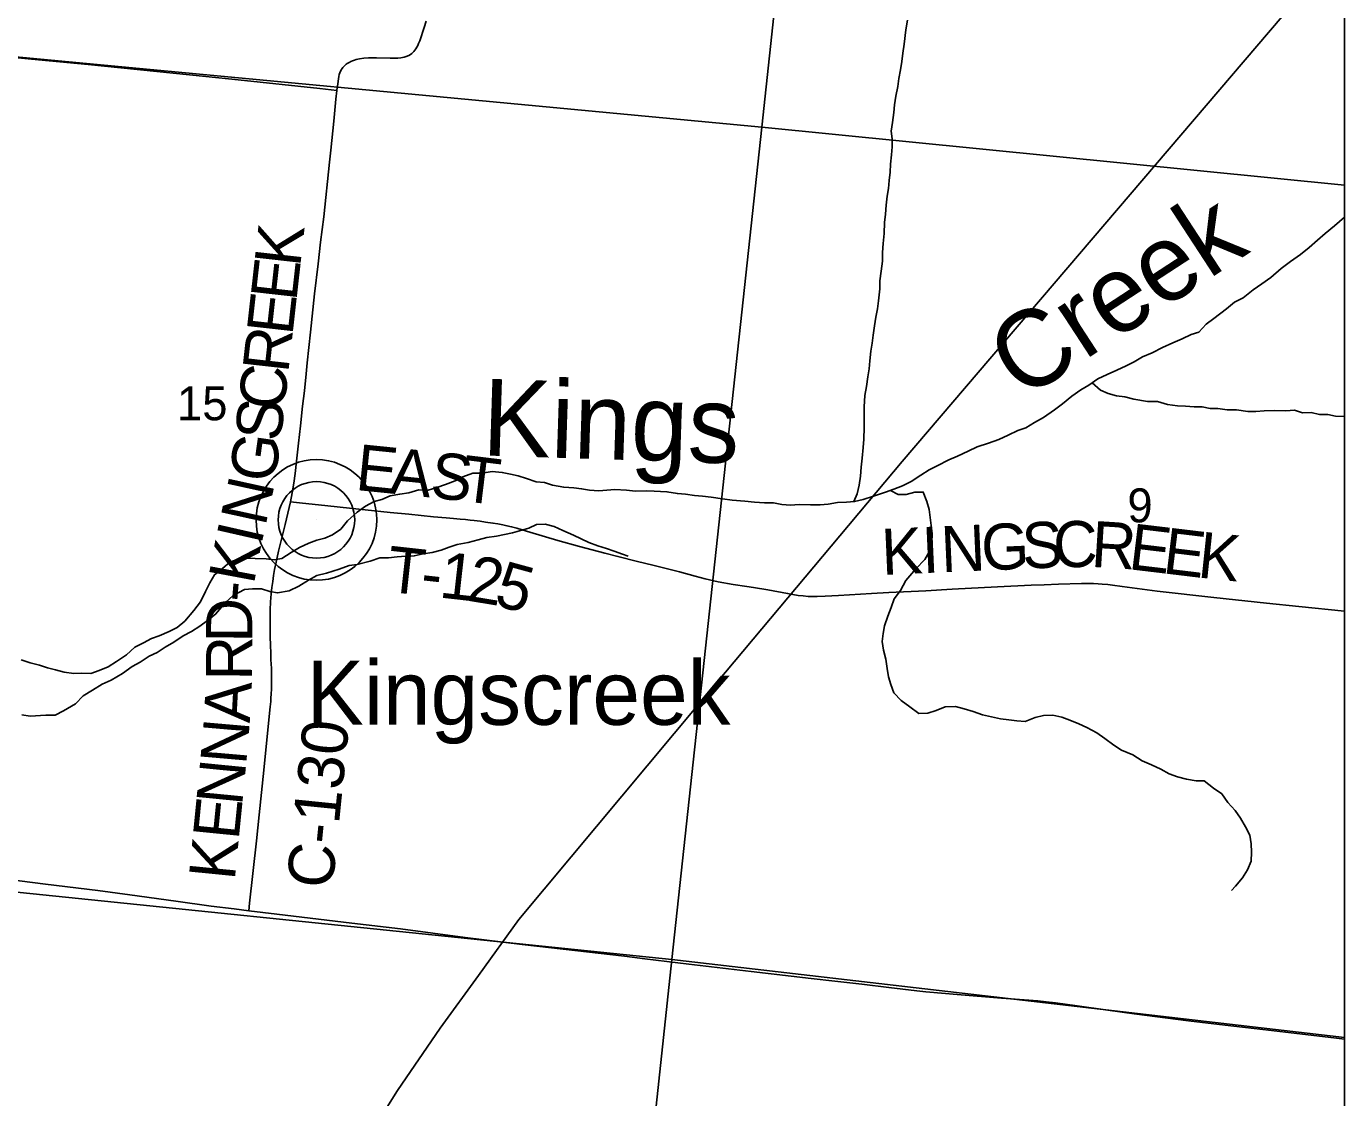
# Model space of a CAD drawing. Extents: x 0 to 1067, y 0 to 440.
# Drawn here: x 803.215 to 804.84, y 355.137 to 356.458 of the extents above; entities that cross this region are included whole.
import ezdxf

# ---------------------------------------------------------------- set-up
doc = ezdxf.new("R2010")
doc.units = 0
for name, color, linetype in [('GM_X_County_Road', 7, 'Continuous'), ('GM_X_County_Road_Text', 7, 'Continuous'), ('GM_X_Minor_River', 7, 'Continuous'), ('GM_X_Minor_River_Text', 7, 'Continuous'), ('GM_X_Rail_Line', 7, 'Continuous'), ('GM_X_Section', 7, 'Continuous'), ('GM_X_Section_Text', 7, 'Continuous'), ('GM_X_State_Route', 7, 'Continuous'), ('GM_X_Township_Road', 7, 'Continuous'), ('GM_X_Township_Road_Text', 7, 'Continuous'), ('GM_X_Unincorporated', 7, 'Continuous'), ('GM_X_Unincorporated_Location', 7, 'Continuous'), ('GM_X_Unincorporated_Text', 7, 'Continuous'), ('GM_X_US_Shield', 7, 'Continuous')]:
    doc.layers.add(name, color=color, linetype=linetype)

msp = doc.modelspace()

# ---------------------------------------------------------------- linework, layer by layer
at = {"layer": 'GM_X_County_Road'}
for points in [[(803.5978, 356.3789), (803.5982, 356.3827), (803.5987, 356.3867), (803.5992, 356.3905), (803.5996, 356.3931), (803.6001, 356.3959), (803.6007, 356.3984), (803.6014, 356.4004), (803.6019, 356.4018), (803.6026, 356.4032), (803.6032, 356.4044), (803.6041, 356.4058), (803.605, 356.407), (803.6059, 356.4081), (803.6071, 356.4094), (803.608, 356.4102), (803.6093, 356.4112), (803.6104, 356.412), (803.612, 356.413), (803.6136, 356.4138), (803.6151, 356.4146), (803.6168, 356.4153), (803.6195, 356.4162), (803.6215, 356.4169), (803.6256, 356.4178), (803.6311, 356.4186), (803.6366, 356.4189), (803.6465, 356.419), (803.6633, 356.4188), (803.6691, 356.4188), (803.6729, 356.4188), (803.6764, 356.4191), (803.6807, 356.42), (803.6842, 356.4212), (803.6873, 356.4225), (803.6902, 356.4245), (803.6927, 356.4269), (803.695, 356.4301), (803.6974, 356.4342), (803.6985, 356.4368), (803.6998, 356.44), (803.7053, 356.4566), (803.708, 356.4641)], [(803.5406, 355.8716), (803.5426, 355.8828), (803.5445, 355.8947), (803.5461, 355.9064), (803.548, 355.9217), (803.5505, 355.9439), (803.5527, 355.9653), (803.5555, 355.9893), (803.5576, 356.0085), (803.5598, 356.0294), (803.5612, 356.0431), (803.5652, 356.0807), (803.5701, 356.128), (803.5745, 356.1651), (803.5777, 356.1919), (803.5815, 356.223), (803.5888, 356.2906), (803.5903, 356.3054), (803.5941, 356.3409), (803.5966, 356.3682), (803.5978, 356.3789)], [(803.4892, 355.3672), (803.4902, 355.3767), (803.4986, 355.4533), (803.5019, 355.4855), (803.5076, 355.5405), (803.5123, 355.5862), (803.5156, 355.6186), (803.5162, 355.6254), (803.5165, 355.6295), (803.5169, 355.6346), (803.5172, 355.6403), (803.5173, 355.6451), (803.5173, 355.65), (803.5173, 355.6559), (803.5171, 355.6624), (803.517, 355.6669), (803.5168, 355.6711), (803.5165, 355.6775), (803.5162, 355.6855), (803.5159, 355.6938), (803.5154, 355.7058), (803.5154, 355.7183), (803.5153, 355.7297), (803.5155, 355.7383), (803.5159, 355.7482), (803.5167, 355.7581), (803.5176, 355.7658), (803.5187, 355.7734), (803.5197, 355.7808), (803.5209, 355.7879), (803.5227, 355.7971), (803.5259, 355.8108), (803.5302, 355.8287), (803.5338, 355.8435), (803.5406, 355.8716)]]:
    msp.add_lwpolyline(points, dxfattribs=at)
at = {"layer": 'GM_X_Minor_River'}
for points in [[(804.235, 355.8718), (804.2391, 355.8813), (804.2418, 355.892), (804.2431, 355.903), (804.244, 355.9144), (804.2452, 355.9254), (804.2465, 355.9384), (804.2473, 355.949), (804.2478, 355.9631), (804.2476, 355.9776), (804.2477, 355.9886), (804.2486, 356.0027), (804.2506, 356.0137), (804.2522, 356.0255), (804.2538, 356.0354), (804.2546, 356.0453), (804.2559, 356.0575), (804.2575, 356.0673), (804.2587, 356.0772), (804.2604, 356.0886), (804.262, 356.0993), (804.2644, 356.1095), (804.2656, 356.1194), (804.2669, 356.1342), (804.2673, 356.1441), (804.2686, 356.1559), (804.2702, 356.1685), (804.2703, 356.1791), (804.2712, 356.1902), (804.2724, 356.2023), (804.2729, 356.216), (804.2742, 356.2263), (804.275, 356.2373), (804.2763, 356.2483), (804.2779, 356.2578), (804.2787, 356.2677), (804.28, 356.278), (804.2804, 356.2879), (804.2813, 356.2993), (804.2825, 356.3095), (804.2822, 356.319), (804.2812, 356.3286), (804.2828, 356.3392), (804.2844, 356.3517), (804.2853, 356.3612), (804.2869, 356.3719), (804.2893, 356.3836), (804.2905, 356.3935), (804.2925, 356.4042), (804.2941, 356.4144), (804.2954, 356.4247), (804.297, 356.4361), (804.2991, 356.4535), (804.3011, 356.4657)], [(804.3281, 355.9109), (804.3376, 355.9158), (804.3522, 355.9232), (804.3629, 355.9277), (804.3759, 355.934), (804.3873, 355.9393), (804.4011, 355.9437), (804.4137, 355.9485), (804.4252, 355.9537), (804.4374, 355.9593), (804.4473, 355.9626), (804.4577, 355.9694), (804.4688, 355.9754), (804.4825, 355.9848), (804.4921, 355.9923), (804.504, 356.0017), (804.5151, 356.0096), (804.5247, 356.0152), (804.5358, 356.023), (804.5473, 356.0286), (804.5591, 356.0339), (804.5706, 356.0391), (804.5805, 356.0443), (804.5909, 356.0503), (804.6027, 356.0551), (804.6157, 356.0618), (804.6283, 356.0678), (804.6398, 356.0726), (804.6509, 356.0778), (804.6604, 356.0808), (804.6693, 356.0906), (804.6789, 356.0977), (804.6946, 356.1094), (804.7042, 356.1176), (804.7149, 356.1232), (804.7275, 356.133), (804.7379, 356.1405), (804.749, 356.148), (804.762, 356.1593), (804.7735, 356.1679), (804.7858, 356.1766), (804.7965, 356.1852), (804.8065, 356.1942), (804.8161, 356.2025), (804.8276, 356.2119), (804.8401, 356.2225)], [(804.529, 356.0182), (804.5391, 356.0093), (804.5486, 356.005), (804.5588, 356.0023), (804.5691, 356.001), (804.5801, 355.9982), (804.5969, 355.9954), (804.6094, 355.9953), (804.6219, 355.9917), (804.6341, 355.9897), (804.644, 355.9896), (804.6547, 355.9887), (804.6646, 355.9886), (804.6744, 355.9866), (804.684, 355.9865), (804.6954, 355.9849), (804.7068, 355.9851), (804.7209, 355.9831), (804.7308, 355.983), (804.741, 355.9837), (804.7532, 355.9843), (804.7677, 355.9838), (804.7784, 355.9844), (804.7882, 355.9813), (804.7989, 355.9815), (804.8092, 355.9792), (804.8194, 355.9791), (804.8289, 355.9771), (804.8401, 355.9766)], [(803.2309, 355.6701), (803.2408, 355.6666), (803.2507, 355.6642), (803.2617, 355.6614), (803.2735, 355.6598), (803.283, 355.6601), (803.2944, 355.6596), (803.3047, 355.6633), (803.3158, 355.6682), (803.3261, 355.6745), (803.3384, 355.6828), (803.3488, 355.6922), (803.3595, 355.6975), (803.369, 355.7031), (803.3786, 355.7064), (803.3908, 355.7116), (803.4008, 355.7165), (803.4103, 355.7244), (803.4215, 355.7376), (803.4296, 355.7482), (803.4358, 355.7608), (803.4412, 355.7718), (803.447, 355.7816), (803.4566, 355.7891), (803.4662, 355.7974), (803.4761, 355.8004), (803.4868, 355.8022), (803.4971, 355.8017), (803.5104, 355.8012), (803.5203, 355.8), (803.5298, 355.8018), (803.5413, 355.8089), (803.5516, 355.8153), (803.5631, 355.8205), (803.573, 355.8242), (803.583, 355.8268), (803.5925, 355.8309), (803.6025, 355.838), (803.611, 355.8482), (803.6229, 355.8588), (803.6332, 355.8663), (803.6435, 355.8719), (803.6531, 355.8745), (803.6634, 355.879), (803.6752, 355.8811), (803.6863, 355.8825), (803.6989, 355.8862), (803.7103, 355.8861), (803.721, 355.8891), (803.7317, 355.8928), (803.7435, 355.8976), (803.7531, 355.9025), (803.7653, 355.9069), (803.7767, 355.9068), (803.7893, 355.909), (803.8015, 355.9077), (803.8117, 355.9057), (803.8212, 355.9037), (803.8315, 355.9002), (803.8436, 355.8963), (803.8535, 355.8954), (803.8634, 355.8919), (803.8775, 355.8895), (803.89, 355.8889), (803.8995, 355.8877), (803.909, 355.8861), (803.9208, 355.8852), (803.9406, 355.8866), (803.9547, 355.886), (803.9658, 355.8848), (803.9791, 355.885), (803.989, 355.8846), (804.0046, 355.884), (804.0175, 355.8816), (804.0274, 355.8808), (804.0388, 355.8795), (804.0483, 355.8786), (804.059, 355.8774), (804.073, 355.8754), (804.0852, 355.8737), (804.1008, 355.8724), (804.1126, 355.8712), (804.1248, 355.8703), (804.1362, 355.8702), (804.1464, 355.8682), (804.1571, 355.8673), (804.1678, 355.8683), (804.1815, 355.8678), (804.1937, 355.8677), (804.2036, 355.8687), (804.215, 355.8705), (804.2261, 355.8712), (804.236, 355.8718), (804.2466, 355.8744), (804.2592, 355.8785), (804.2741, 355.8833), (804.2844, 355.887), (804.2951, 355.8914), (804.3059, 355.8967), (804.3177, 355.9045), (804.3281, 355.9109)], [(804.2801, 355.8854), (804.2897, 355.8804), (804.2996, 355.8807), (804.3103, 355.8833), (804.3206, 355.8836), (804.3251, 355.8721), (804.328, 355.8622), (804.3291, 355.8523), (804.3305, 355.8423), (804.3315, 355.832), (804.3311, 355.8214), (804.3291, 355.8119), (804.3225, 355.8005), (804.3114, 355.7888), (804.299, 355.7745), (804.2925, 355.762), (804.2848, 355.7518), (804.2812, 355.7411), (804.277, 355.7305), (804.273, 355.7187), (804.2714, 355.7092), (804.2698, 355.6993), (804.2716, 355.6887), (804.2746, 355.6776), (804.276, 355.6661), (804.2778, 355.6558), (804.2808, 355.6463), (804.2845, 355.636), (804.2932, 355.6264), (804.3041, 355.6186), (804.3151, 355.6105), (804.3261, 355.6108), (804.3364, 355.6141), (804.3475, 355.6186), (804.3605, 355.6192), (804.3711, 355.6164), (804.3821, 355.6129), (804.3935, 355.609), (804.4049, 355.6062), (804.4159, 355.6038), (804.4262, 355.6026), (804.4361, 355.6013), (804.4464, 355.6005), (804.4586, 355.6057), (804.4689, 355.6079), (804.4803, 355.6085), (804.4913, 355.6061), (804.5012, 355.6022), (804.5126, 355.5979), (804.5221, 355.5932), (804.5346, 355.5866), (804.5444, 355.5797), (804.5554, 355.5716), (804.5652, 355.5654), (804.5789, 355.5595), (804.5906, 355.5522), (804.602, 355.5471), (804.6137, 355.542), (804.624, 355.5362), (804.6342, 355.5323), (804.6452, 355.5295), (804.657, 355.5275), (804.6669, 355.5274), (804.6786, 355.5185), (804.6888, 355.5112), (804.696, 355.5008), (804.705, 355.4908), (804.7118, 355.4812), (804.7178, 355.4709), (804.7234, 355.4605), (804.7248, 355.4499), (804.7255, 355.4396), (804.7247, 355.4285), (804.7204, 355.4175), (804.7142, 355.4077), (804.7057, 355.3975), (804.7007, 355.3922)], [(803.2094, 355.609), (803.2197, 355.6073), (803.2387, 355.6083), (803.2505, 355.6086), (803.2605, 355.6138), (803.2754, 355.6224), (803.285, 355.6322), (803.2965, 355.6394), (803.3084, 355.6465), (803.3195, 355.6517), (803.3336, 355.66), (803.3455, 355.6683), (803.3554, 355.6739), (803.3662, 355.681), (803.3761, 355.6859), (803.3861, 355.6923), (803.3968, 355.6983), (803.4083, 355.7061), (803.4186, 355.7114), (803.4286, 355.7181), (803.4381, 355.7253), (803.4481, 355.7328), (803.4604, 355.7472), (803.47, 355.7559), (803.4838, 355.7633), (803.4937, 355.7644), (803.5047, 355.7643), (803.515, 355.7611), (803.5245, 355.7591), (803.539, 355.7617), (803.5508, 355.7677), (803.5627, 355.7748), (803.573, 355.7808), (803.5849, 355.7837), (803.6005, 355.7885), (803.6127, 355.793), (803.6227, 355.7944), (803.6387, 355.7984), (803.6505, 355.8025), (803.6612, 355.8024), (803.6722, 355.8038), (803.6829, 355.8045), (803.6932, 355.8048), (803.7039, 355.8073), (803.7153, 355.8091), (803.7264, 355.8117), (803.7363, 355.8158), (803.7459, 355.8187), (803.7596, 355.8213), (803.7718, 355.8246), (803.7825, 355.8275), (803.7947, 355.8293), (803.8042, 355.8311), (803.8141, 355.8333), (803.8344, 355.8392), (803.8439, 355.8437), (803.8546, 355.844), (803.8656, 355.8412), (803.8762, 355.8361), (803.8895, 355.8303), (803.9085, 355.8213), (803.9195, 355.8171), (803.9301, 355.8139), (803.9396, 355.8108), (803.9498, 355.8069), (803.9567, 355.8045)], [(803.2085, 355.6768), (803.2195, 355.6729), (803.2309, 355.6701)]]:
    msp.add_lwpolyline(points, dxfattribs=at)
at = {"layer": 'GM_X_Rail_Line'}
msp.add_lwpolyline([(802.6661, 353.2687), (802.697, 353.3096), (802.7308, 353.3638), (802.8122, 353.4875), (802.8565, 353.5668), (802.8978, 353.6472), (802.9601, 353.7689), (803.2011, 354.2396), (803.4754, 354.7705), (803.5751, 354.9733), (803.6255, 355.0706), (803.6726, 355.1455), (803.7251, 355.2226), (803.7723, 355.2875), (803.8221, 355.3565), (804.0447, 355.6231), (804.2946, 355.9212), (804.7631, 356.4702), (804.8401, 356.5624)], dxfattribs=at)
at = {"layer": 'GM_X_Section'}
for points in [[(804.224, 357.2865), (804.1217, 356.3334), (803.0664, 356.4332), (803.1843, 357.3948)], [(803.0664, 356.4332), (804.1217, 356.3334), (804.0106, 355.307), (802.9708, 355.4138)], [(804.0106, 355.307), (803.9043, 354.3108), (802.8724, 354.4357), (802.9708, 355.4138)]]:
    msp.add_lwpolyline(points, close=True, dxfattribs=at)
at = {"layer": 'GM_X_State_Route'}
for points in [[(802.9737, 355.4214), (802.9777, 355.4215), (803.005, 355.4227), (803.0192, 355.4229), (803.0322, 355.4227), (803.0471, 355.4221), (803.0657, 355.4208), (803.0873, 355.4189), (803.1132, 355.416), (803.1706, 355.4088), (803.2384, 355.4001), (803.3031, 355.392), (803.3425, 355.3867), (803.3991, 355.379), (803.4428, 355.373), (803.4712, 355.3694), (803.4892, 355.3672)], [(803.4892, 355.3672), (803.5236, 355.3631), (803.6161, 355.3519), (803.676, 355.3449), (803.756, 355.3344), (803.8263, 355.3255), (803.8769, 355.32), (803.9522, 355.311), (803.9774, 355.3079), (804.0316, 355.3015), (804.1086, 355.2924), (804.1826, 355.2838), (804.2116, 355.2804), (804.2449, 355.2765), (804.2782, 355.2725), (804.3128, 355.2684), (804.3239, 355.2672), (804.3623, 355.2639), (804.4172, 355.2596), (804.462, 355.256), (804.4721, 355.255), (804.4836, 355.2537), (804.5076, 355.2504), (804.5481, 355.2445), (804.5807, 355.2399), (804.6478, 355.2315), (804.6928, 355.226), (804.7391, 355.2209), (804.781, 355.2159), (804.8267, 355.2104), (804.8401, 355.2088)]]:
    msp.add_lwpolyline(points, dxfattribs=at)
at = {"layer": 'GM_X_Township_Road'}
for points in [[(804.8401, 353.205), (804.8401, 357.6021), (800.0635, 357.6021)], [(803.0686, 356.432), (803.1204, 356.4272), (803.1835, 356.421), (803.2299, 356.4167), (803.2911, 356.4108), (803.436, 356.396), (803.4762, 356.3919), (803.5766, 356.3812), (803.5978, 356.3789)], [(803.5406, 355.8716), (803.5553, 355.87), (803.5828, 355.8671), (803.6017, 355.8651), (803.6635, 355.8585), (803.6866, 355.8563), (803.7168, 355.8532), (803.7323, 355.8517), (803.7414, 355.8509), (803.7497, 355.8502), (803.7563, 355.8496), (803.762, 355.849), (803.7668, 355.8485), (803.7745, 355.8476), (803.7809, 355.8466), (803.79, 355.8453), (803.7963, 355.8442), (803.8024, 355.8431), (803.8073, 355.8421), (803.8132, 355.8407), (803.8194, 355.839), (803.8263, 355.8369), (803.8358, 355.8339), (803.8703, 355.8237), (803.8967, 355.8165), (803.928, 355.8083), (803.9443, 355.8042), (803.9684, 355.798), (803.9871, 355.7935), (804.0202, 355.7851), (804.0393, 355.7799), (804.0519, 355.7765), (804.0678, 355.773), (804.0861, 355.7697), (804.1033, 355.7669), (804.1112, 355.7657), (804.129, 355.7628), (804.1534, 355.7585), (804.1663, 355.7562), (804.1725, 355.7554), (804.1787, 355.7549), (804.19, 355.7549), (804.1999, 355.7552), (804.2161, 355.7562), (804.257, 355.7584), (804.2781, 355.7595), (804.324, 355.7618), (804.3563, 355.7637), (804.4121, 355.7667), (804.4537, 355.7687), (804.4695, 355.7693), (804.4872, 355.7699), (804.5157, 355.7707), (804.5241, 355.7706), (804.5307, 355.7706), (804.5363, 355.7704), (804.5414, 355.77), (804.5481, 355.7694), (804.5541, 355.7686), (804.566, 355.767), (804.6089, 355.7613), (804.6787, 355.7535), (804.7436, 355.7466), (804.7838, 355.7425), (804.8401, 355.7365)]]:
    msp.add_lwpolyline(points, dxfattribs=at)
at = {"layer": 'GM_X_Unincorporated'}
for radius in [0.0744, 0.0472]:
    msp.add_circle((803.5725, 355.8492), radius, dxfattribs=at)
at = {"layer": 'GM_X_Unincorporated_Location'}
msp.add_line((803.5725, 355.8492), (803.5725, 355.8492), dxfattribs=at)
at = {"layer": 'GM_X_US_Shield'}
for points in [[(804.8401, 356.2621), (804.8401, 357.2164), (804.224, 357.2865), (804.1217, 356.3334)], [(804.8401, 355.211), (804.8401, 356.2621), (804.1217, 356.3334), (804.0106, 355.307)], [(804.8401, 354.2229), (804.8401, 355.211), (804.0106, 355.307), (803.9043, 354.3108)]]:
    msp.add_lwpolyline(points, close=True, dxfattribs=at)

# ---------------------------------------------------------------- texts
at = {"layer": 'GM_X_County_Road_Text'}
for s, height, rotation, p in [('K', 0.0568, 83.5974, (803.5524, 356.1602)), ('E', 0.0568, 83.5969, (803.5477, 356.118)), ('E', 0.0568, 83.5969, (803.5429, 356.0758)), ('R', 0.0568, 83.5987, (803.5377, 356.0294)), ('C', 0.0568, 83.5987, (803.5325, 355.983)), ('S', 0.0568, 83.5377, (803.5282, 355.9449)), ('G', 0.0568, 82.1002, (803.5211, 355.8938)), ('N', 0.0568, 77.6063, (803.5095, 355.8402)), ('I', 0.0568, 77.185, (803.5043, 355.817)), ('K', 0.0568, 79.3638, (803.4952, 355.7684)), ('-', 0.0568, 85.2091, (803.4934, 355.7467)), ('D', 0.0568, 89.831, (803.4933, 355.6979)), ('R', 0.0568, 89.6123, (803.493, 355.651)), ('A', 0.0568, 86.9826, (803.4903, 355.5982)), ('C-130', 0.05682, 84.2353, (803.5922, 355.3933)), ('N', 0.0568, 85.0315, (803.4858, 355.5463)), ('N', 0.0568, 84.3605, (803.4808, 355.4958)), ('E', 0.0568, 84.338, (803.4766, 355.4535)), ('K', 0.0568, 84.3409, (803.4717, 355.4037))]:
    msp.add_text(s, height=height, rotation=rotation, dxfattribs=at).set_placement(p)
at = {"layer": 'GM_X_Minor_River_Text'}
for s, height, rotation, p in [('Creek', 0.09461, 33.1206, (804.4425, 355.9956)), ('Kings', 0.0947, 358.1764, (803.7761, 355.9288))]:
    msp.add_text(s, height=height, rotation=rotation, dxfattribs=at).set_placement(p)
at = {"layer": 'GM_X_Section_Text'}
for s, height, p in [('15', 0.04186, (803.4006, 355.9721)), ('9', 0.0419, (804.5723, 355.8462))]:
    msp.add_text(s, height=height, rotation=0, dxfattribs=at).set_placement(p)
at = {"layer": 'GM_X_Township_Road_Text'}
for s, rotation, p in [('E', 354.1875, (803.6195, 355.8863)), ('A', 354.1836, (803.6618, 355.882)), ('S', 353.9547, (803.7115, 355.8769)), ('T', 353.027, (803.7494, 355.8729)), ('G', 2.496, (804.3933, 355.7867)), ('S', 2.4858, (804.4433, 355.7889)), ('C', 1.0499, (804.4812, 355.7905)), ('R', 356.4383, (804.5266, 355.7914)), ('E', 353.2216, (804.5724, 355.7886)), ('K', 2.496, (804.2701, 355.7813)), ('I', 2.4947, (804.3201, 355.7835)), ('N', 2.4952, (804.3434, 355.7845)), ('E', 353.1137, (804.6146, 355.7836)), ('K', 353.9936, (804.6577, 355.7784)), ('T', 353.666, (803.6573, 355.761)), ('1', 353.565, (803.7227, 355.7537)), ('2', 350.7225, (803.7567, 355.7499)), ('5', 344.6687, (803.7897, 355.7446)), ('-', 353.6408, (803.6995, 355.7563))]:
    msp.add_text(s, height=0.0568, rotation=rotation, dxfattribs=at).set_placement(p)
at = {"layer": 'GM_X_Unincorporated_Text'}
msp.add_text('Kingscreek', height=0.07898, rotation=0, dxfattribs=at).set_placement((803.5606, 355.5965))

doc.saveas('drawing.dxf')
